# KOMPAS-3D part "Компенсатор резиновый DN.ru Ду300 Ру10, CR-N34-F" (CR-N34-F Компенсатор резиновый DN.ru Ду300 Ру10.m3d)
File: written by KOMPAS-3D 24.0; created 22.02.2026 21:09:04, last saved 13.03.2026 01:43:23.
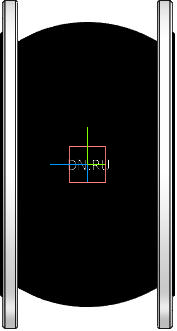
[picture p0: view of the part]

Document properties: Автор: DN.RU; Полное имя файла: CR-N34-F Компенсатор резиновый DN.ru Ду300 Ру10.cdw

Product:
- Body: Твердое тело2  | qty 1
    Масса: 97.65083
- Part/product: Компенсатор резиновый DN.ru Ду300 Ру10  | designation CR-N34-F
    Масса: 30
    Раздел спецификации: Прочие изделия
    Форматы листов документа: A2
    Комментарий: D140-02097
    Примечание: D140-02097
    additional columns: Типовые

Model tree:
1. Твердое тело2  (labels: Твердое тело2)

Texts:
  CR-N34-F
